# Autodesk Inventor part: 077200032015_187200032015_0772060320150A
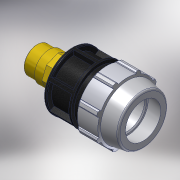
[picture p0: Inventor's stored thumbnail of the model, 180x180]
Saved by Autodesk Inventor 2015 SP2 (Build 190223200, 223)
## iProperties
Created: 2017-02
Part Number: 077200032015_187200032015_0772060320150A
Material: PVC-Piping
Description: PLASSON MALE ADAPTOR INTEGRAL BRASS THREAD 32-1.1/2"
Document SubType Name: Modeling
Designer: KIM
Mass: 92.6774 g
Surface Area: 199.44 cm^2
Volume: 66.1981 cm^3
Density: 1.4 g/cm^3
Appearance: PTFE
Author: KIM
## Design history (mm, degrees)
derived "07720.ipt"
feature "Solid1::07720.ipt"
tag "TaggingFeature1"
body "Solid1"
other parameters: "d2" = 32, "d4" = 20.28571, "d5" = 20.28571, "d7" = 64, "d8" = 48, "d9" = 20.28571, "d11" = 4.05714, "d12" = 51.2, "d13" = 120 deg, "d14" = 48, "d15" = 10 deg, "d16" = 57.6, "d18" = 1.6, "d19" = 35 deg, "d20" = 17.5 deg, "d21" = 59.52, "d23" = 0, "d25" = 360 deg, "d27" = 1.28, "d34" = 3.2, "d36" = 0, "d42" = 28.4, "d43" = 1.92, "d46" = 0.96, "d49" = 83, "d51" = 142, "d53" = 0.64, "d55" = 360 deg, "d59" = 28.4, "d60" = 47.803, "d61" = 52.5833, "d62" = 22, "d63" = 47.33333, "d64" = 33.4621, "d65" = 142, "d66" = 13.54406, "d67" = 0, "d68" = 0.64, "d71" = 30 deg, "d72" = 43.0227, "d_" = 32, "E_" = 64, "H_" = 142, "l_" = 83, "l_2" = 22, "R_" = 47.803, "d73" = 22.57343
